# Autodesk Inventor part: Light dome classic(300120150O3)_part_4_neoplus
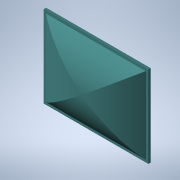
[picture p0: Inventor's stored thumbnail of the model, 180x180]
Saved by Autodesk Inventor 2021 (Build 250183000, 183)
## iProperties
Created: 2026-04
Part Number: Light dome classic(300120150O3)_part_4_neoplus
Material: Generic
Catalog Web Link: www.3dfindit.com
Description: Light dome classic_part_4_neoplus-
Vendor: KINGSPAN
Document SubType Name: Modeling
Designer: psAdmin
Manufacturer: KINGSPAN
Mass: 165695 g
Surface Area: 32897.4 cm^2
Volume: 165695 cm^3
Density: 1 g/cm^3
Appearance: PSOLRGB-194-255-255
Category: PARTsolutions
Company: KINGSPAN
Title: Light dome classic(300120150O3)_part_4_neoplus
Author: Cadenas PARTsolutions
PSOL_IDENT_0: {$CADENAS_DATA/23d-libs/kingspan_kla/light_dome_classic_neoplus/parts/part_4.prj},278 {VTYP=3D},{NB=
PSOL_IDENT_1: Light dome classic(300120150O3)_part_4_neoplus},{LINA=Light dome classic(300120150O3)_part_4_neoplus
PSOL_IDENT_2: },{NN=Light dome classic_part_4_neoplus},{DATE=20.03.2025 09:30:52},{GEOMDATE=01.07.2024 05:57:57},{
PSOL_IDENT_3: VERSION=},{LINEID=10},{WBVAR=LODLEVEL,L,W,TG,TS},{WBNUMERIC=W}  {NB=Light dome classic(300120150O3)_
PSOL_IDENT_4: part_4_neoplus},{LINA=Light dome classic(300120150O3)_part_4_neoplus},{KT=DUMMY},{IDNR=},{PN=Light d
PSOL_IDENT_5: ome classic},{LODLEVEL=300},{L=120},{W=150},{WX=120,150,180,240,270,300},{TG=O},{TS=3},{TSX='3','acr
PSOL_IDENT_6: ylic shell with Polycarbonate','4','2 layers of acrylic shell + 1  Polycarbonate panel','5','1 layer
PSOL_IDENT_7: s of acrylic shell + 1 polycarbonate panel + aerogel'},{LX=1200},{XWX=1500},{VER=2},{HEI=1181.607},{
PSOL_IDENT_8: TOP=400},{NO=2},{HEIGHT=220},{SEC=30}
NB: Light dome classic(300120150O3)_part_4_neoplus
NN: Light dome classic_part_4_neoplus
NBSYN: $PN.($LODLEVEL.$L.$W.$TG.$TS.)_part_4_neoplus
LINA: Light dome classic(300120150O3)_part_4_neoplus
CATALOG: Light + Air
PN: Light dome classic
LODLEVEL: 300
L: 120
W: 150
TG: opal
TS: acrylic shell with Polycarbonate
SUPPLIER: KINGSPAN
ARTICLENO: Light dome classic(300120150O3)_part_4_neoplus
BOMINFO: Light dome classic(300120150O3)_part_4_neoplus
CREATOR: CADENAS GmbH
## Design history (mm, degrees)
sketch "Sketch_9"
  geometry: L1 (650, 0)-(650, 106.946); L2 (-650, 106.946)-(-650, 0); L3 (-650, 0)-(650, 0); A1 r 1234.392 centre (0, -942.446) between (650, 106.946) and (-650, 106.946)
  constraints: 6 end point, 2 point on circle, 1 centre point
extrude "Extrusion1" join sketch "Sketch_9" stored distance "d0" = 1500; taper "d1" = 0 deg
sketch "Sketch_2"
  geometry: L1 (756, 103.596)-(-756, 103.596); L2 (-756, 103.596)-(-756, 71.946); L3 (-756, 71.946)-(756, 71.946); L4 (756, 71.946)-(756, 103.596)
  constraints: 8 end point
extrude "Extrusion2" join sketch "Sketch_2" stored distance "d2" = 2400; taper "d3" = 0 deg
sketch "Sketch_3"
  geometry: L1 (-630, 103.596)-(-630, 71.946); L2 (-630, 71.946)-(630, 71.946); L3 (630, 71.946)-(630, 103.596); L4 (630, 103.596)-(-630, 103.596)
  constraints: 8 end point
extrude "Extrusion3" join sketch "Sketch_3" stored distance "d4" = 3000; taper "d5" = 0 deg
sketch "Sketch_4"
  geometry: L1 (-2033, 103.596)-(-2033, -128.054); L2 (-2033, -128.054)-(2033, -128.054); L3 (2033, -128.054)-(2033, 103.596); L4 (2033, 103.596)-(533, 103.596); L5 (533, 103.596)-(533, 71.946); L6 (533, 71.946)-(-533, 71.946); L7 (-533, 71.946)-(-533, 103.596); L8 (-533, 103.596)-(-2033, 103.596)
  constraints: 16 end point
extrude "Extrusion4" cut sketch "Sketch_4" stored distance "d6" = 3000; taper "d7" = 0 deg
sketch "Sketch_17"
  geometry: L1 (1000, -16104.45)-(-1000, -16104.45); L2 (-135, 100)-(-135, -106.95); L3 (-135, -106.95)-(135, -106.95); L4 (135, -106.95)-(135, 100); A1 r 1825 centre (0, -1720) between (135, 100) and (-135, 100)
  constraints: 8 end point, 2 point on circle, 1 centre point
revolve "Revolution1" sketch "Sketch_17" stored, may be unused: angle "d8" = 360 deg
sketch "Sketch_13"
  geometry: L1 (682, 61.946)-(682, 103.596); L2 (682, 103.596)-(630, 103.596); L3 (630, 103.596)-(630, 71.946); L4 (630, 71.946)-(-630, 71.946); L5 (-630, 71.946)-(-630, 103.596); L6 (-630, 103.596)-(-682, 103.596); L7 (-682, 103.596)-(-682, 61.946); L8 (-682, 61.946)-(682, 61.946)
  constraints: 16 end point
extrude "Extrusion5" join sketch "Sketch_13" stored distance "d9" = 1200; taper "d10" = 0 deg
sketch "Sketch_14"
  geometry: L1 (2150, 103.596)-(682, 103.596); L2 (682, 103.596)-(682, 71.946); L3 (682, 71.946)-(-682, 71.946); L4 (-682, 71.946)-(-682, 103.596); L5 (-682, 103.596)-(-2150, 103.596); L6 (-2150, 103.596)-(-2150, -128.054); L7 (-2150, -128.054)-(2150, -128.054); L8 (2150, -128.054)-(2150, 103.596)
  constraints: 16 end point
extrude "Extrusion6" cut sketch "Sketch_14" stored distance "d11" = 2400; taper "d12" = 0 deg
sketch "Sketch_15"
  geometry: L1 (2024, 1400)-(-2024, 1400); L2 (-2024, 1400)-(-2024, 0); L3 (-2024, 0)-(-533, 0); L4 (-533, 0)-(-533, 103.596); L5 (-533, 103.596)-(-500, 103.596); L6 (-500, 103.596)-(-500, 106.946); L7 (500, 106.946)-(500, 103.596); L8 (500, 103.596)-(533, 103.596); L9 (533, 103.596)-(533, 0); L10 (533, 0)-(2024, 0); L11 (2024, 0)-(2024, 1400); A1 r 768.176 centre (0, -476.23) between (500, 106.946) and (-500, 106.946)
  constraints: 22 end point, 2 point on circle, 1 centre point
extrude "Extrusion7" cut sketch "Sketch_15" stored distance "d13" = 1500; taper "d14" = 0 deg
node "IP_4_XY"
node "IP_4_YZ"
node "IP_4_ZX"
node "IP_4_X"
node "IP_4_Y"
node "IP_4_Z"
node "IP_4_Center"
body "Solid1"
other parameters: "d15" = 0
